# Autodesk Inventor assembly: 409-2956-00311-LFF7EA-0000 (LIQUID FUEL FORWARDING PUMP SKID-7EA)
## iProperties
Created: 2010-09
Part Number: 409-2956-00311-LFF7EA-0000 (LIQUID FUEL FORWARDING PUMP SKID-7EA)
Document SubType Name: Assembly
Designer: S. Boerckel
Mass: 2.68414e+06 g
Surface Area: 779543 cm^2
Volume: 400568 cm^3
Density: 6.70084 g/cm^3
Material: ASSEMBLY
SMR: =<MATERIAL>
Author: S. Boerckel
Revision Number: 0
